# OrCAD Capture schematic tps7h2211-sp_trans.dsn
size B; title: TPS7H2211-SP Radiation-Hardness-Assured (RHA) 14-V, 3.5-A; rev: *; note: Datasheet: SLVSEW6    EVM User Guide: SLVUC17; note: Load Switch
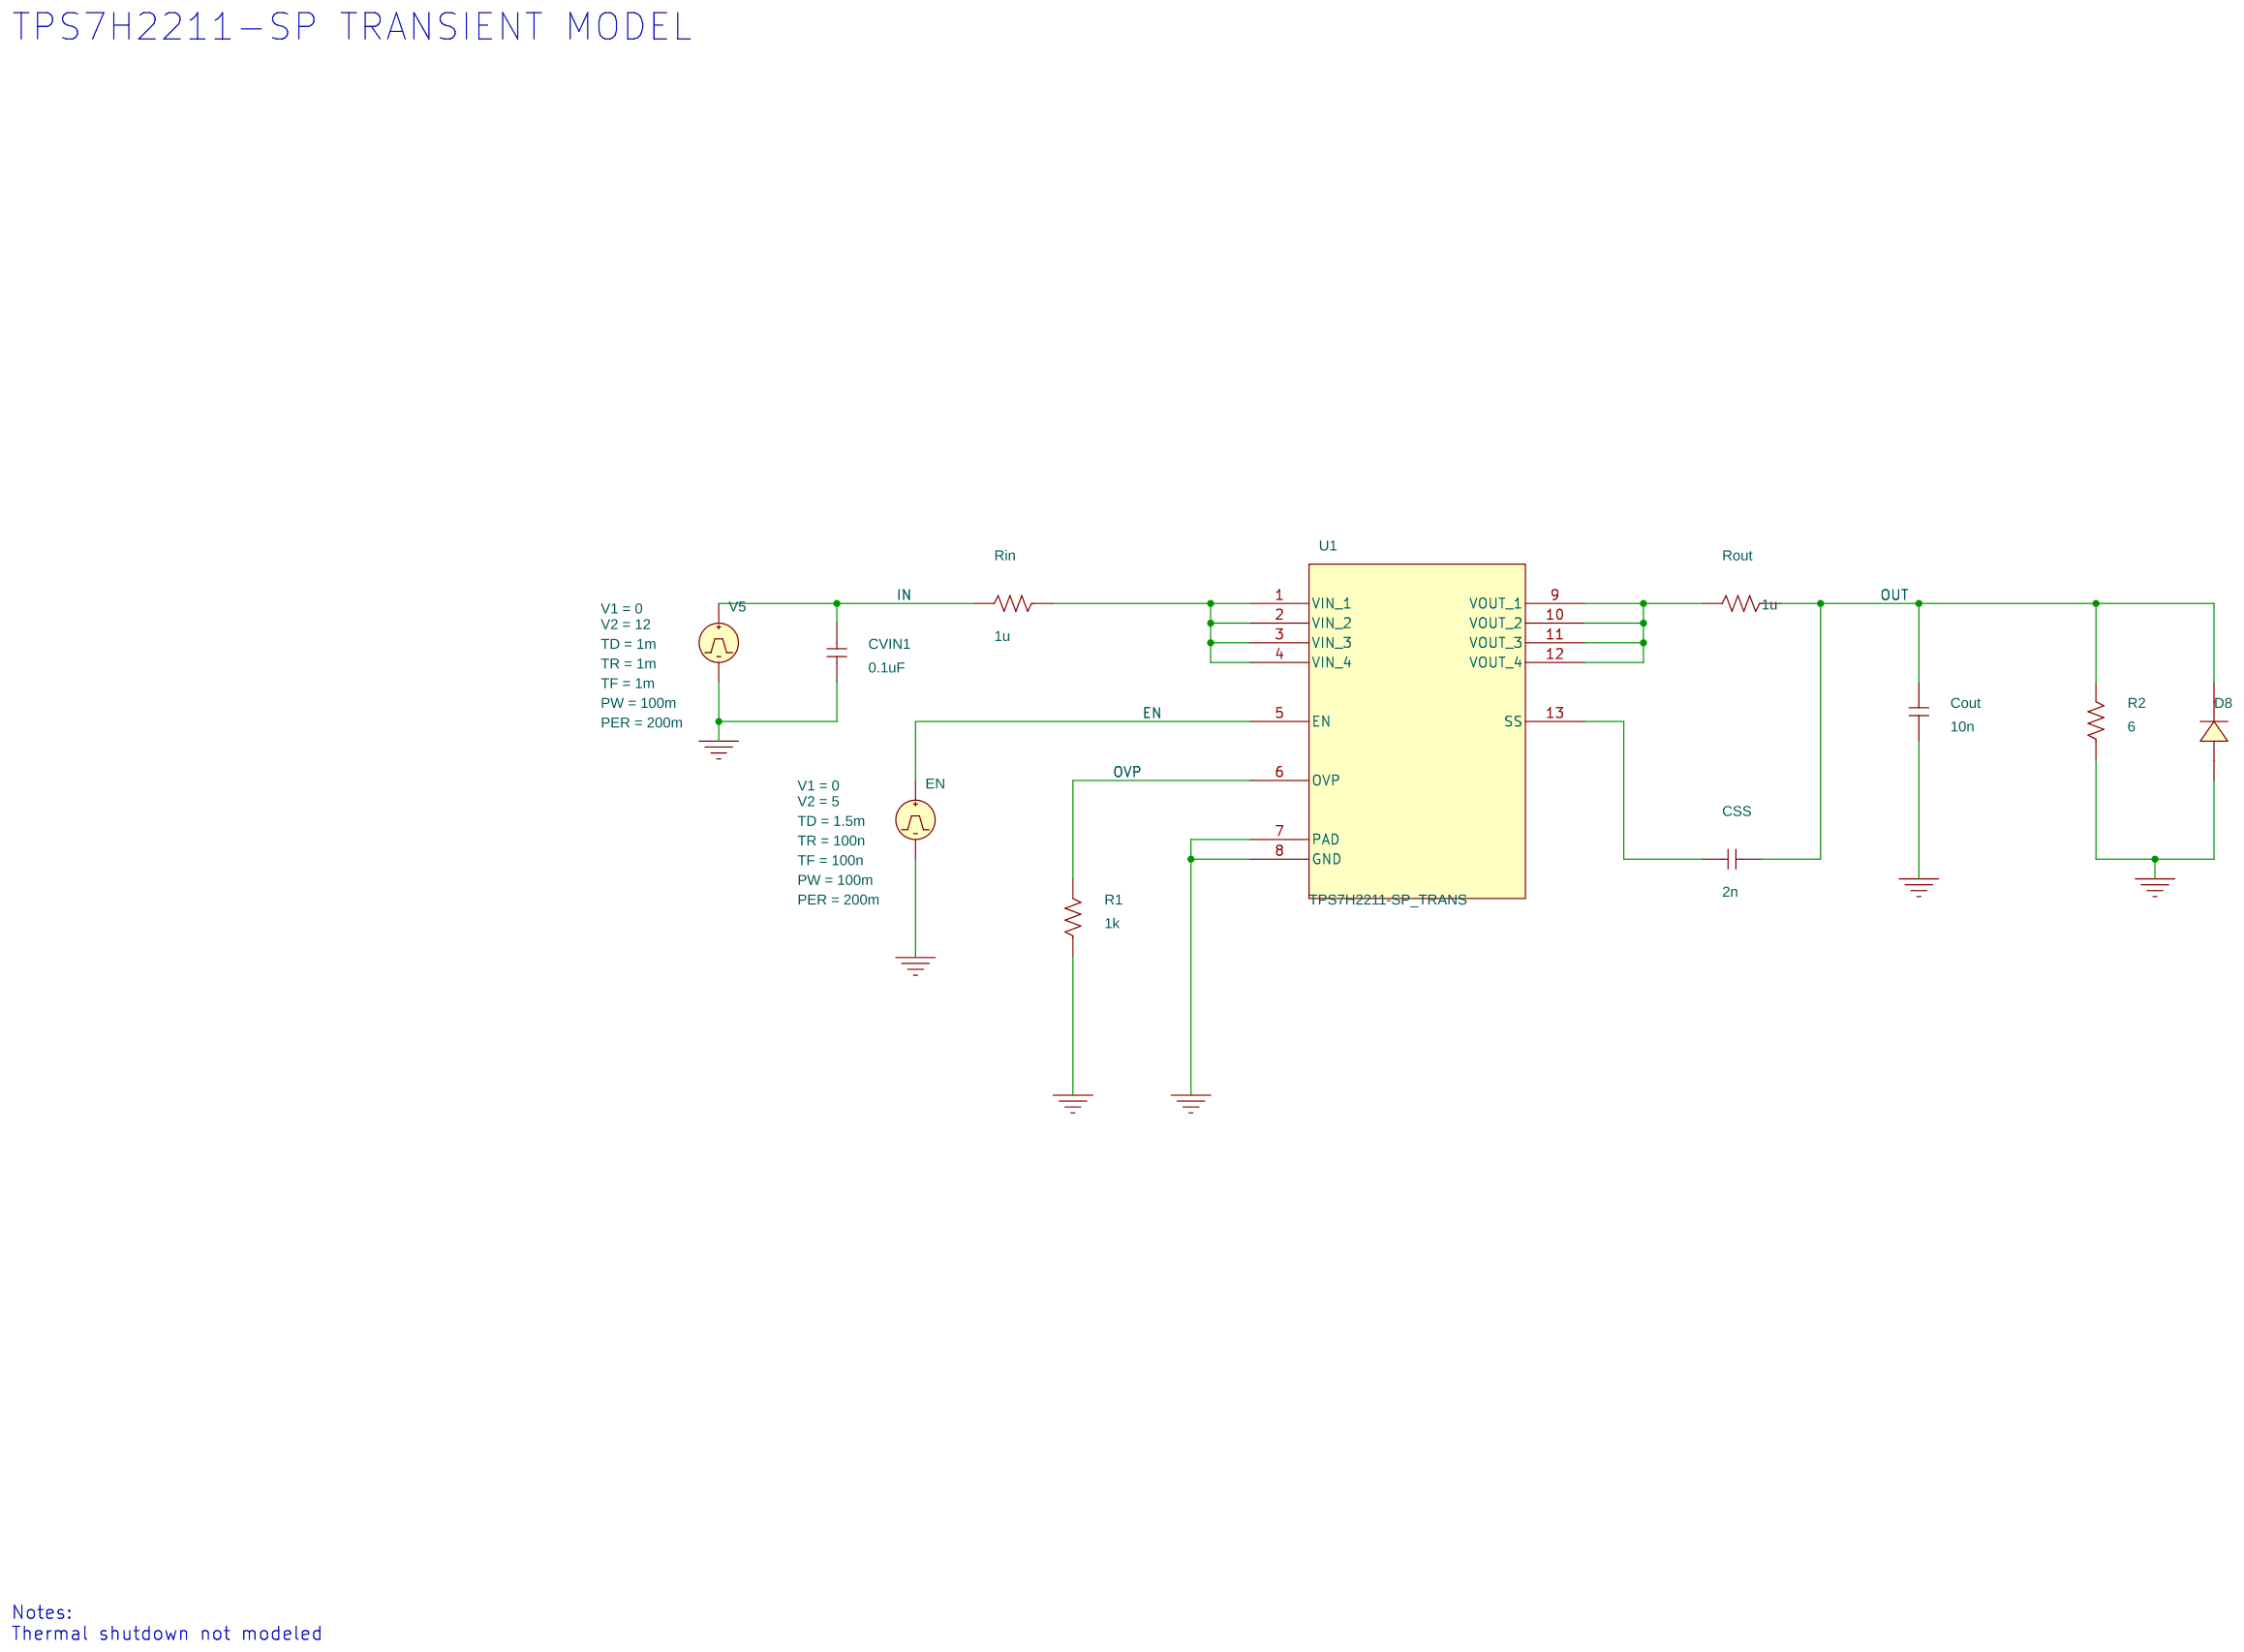
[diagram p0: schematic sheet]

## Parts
Cout  10n  [cap196]
CSS  2n  [RAD/CK05]
CVIN1  0.1uF  [RAD/CK05]
D8  D_D1
EN  VPULSE
R1  1k  [AXRC05]
R2  6  [AXRC05]
Rin  1u  [AX/RC05]
Rout  1u  [AX/RC05]
U1  TPS7H2211-SP_TRANS
V5  VPULSE

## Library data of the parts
Cout CSS CVIN1 = C
D8 = D_D1
EN = VPULSE: PER: 200m; PW: 100m; TD: 1.5m; TF: 100n; TR: 100n; V1: 0; V2: 5
R1 R2 Rin Rout = R
U1 = TPS7H2211-SP_TRANS_0: PSpiceTemplate: X^@REFDES  %VIN_1 %VIN_2 %VIN_3 %VIN_4 %EN %OVP %PAD %GND %VOUT_1 %VOUT_2 %VOUT_3 %VOUT_4 %SS @MODEL
V5 = VPULSE: PER: 200m; PW: 100m; TD: 1m; TF: 1m; TR: 1m; V1: 0; V2: 12

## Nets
0: Cout.1 CVIN1.1 D8.2(A) EN.2(-) R1.1 R2.1 U1.7(PAD) U1.8(GND) V5.2(-)
EN: EN.1(+) U1.5(EN)
IN: CVIN1.2 Rin.2 V5.1(+)
OUT: Cout.2 CSS.1 D8.1(C) R2.2 Rout.1
OVP: R1.2 U1.6(OVP)
N16777452: Rin.1 U1.1(VIN) U1.2(VIN) U1.3(VIN) U1.4(VIN)
N16777501: CSS.2 U1.13(SS)
N16779074: Rout.2 U1.9(VOUT_1) U1.10(VOUT_2) U1.11(VOUT_3) U1.12(VOUT_4)

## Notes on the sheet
- TPS7H2211-SP TRANSIENT MODEL
- Notes:
  Thermal shutdown not modeled
